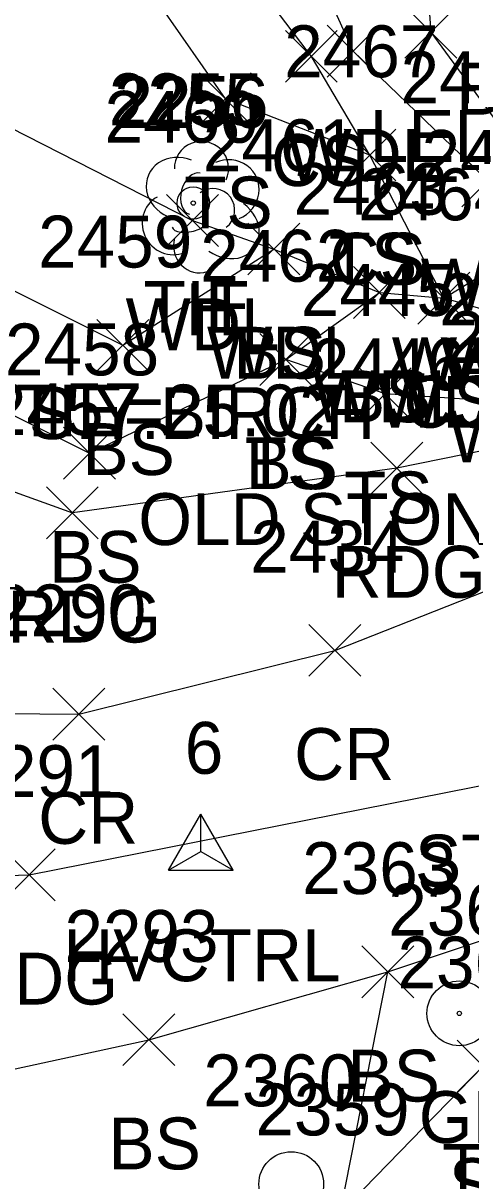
# Model space of a CAD drawing. Extents: x 1512665 to 1513714, y 110636 to 112816.
# Drawn here: x 1513022.1 to 1513039.38, y 110740.23 to 110784.88 of the extents above; entities that cross this region are included whole.
import ezdxf

# ---------------------------------------------------------------- set-up
doc = ezdxf.new("R2010")
doc.units = 0
for name, color, linetype in [('C_A', 7, 'Continuous'), ('C_C', 7, 'Continuous'), ('C_I', 7, 'Continuous'), ('CBP', 7, 'Continuous'), ('CPSM', 7, 'Continuous'), ('L_A', 7, 'Continuous'), ('L_C', 7, 'Continuous'), ('L_I', 7, 'Continuous'), ('L_TIC', 7, 'Continuous'), ('LARO', 7, 'Continuous'), ('LAWA', 7, 'Continuous'), ('LELB', 7, 'Continuous'), ('LTD', 7, 'Continuous'), ('P_A', 7, 'Continuous'), ('P_I', 7, 'Continuous'), ('P_TIC', 7, 'Continuous'), ('PEU', 7, 'Continuous'), ('PRC', 7, 'Continuous'), ('R_A', 7, 'Continuous'), ('R_I', 7, 'Continuous'), ('RGP', 7, 'Continuous')]:
    doc.layers.add(name, color=color, linetype=linetype)

msp = doc.modelspace()

# ---------------------------------------------------------------- linework, layer by layer
at = {"layer": 'CBP'}
for radius in [0.625, 0.0833]:
    msp.add_circle((1513028.667, 110777.939), radius, dxfattribs=at)
at = {"layer": 'CPSM'}
for p, q in [((1513027.711, 110752.208), (1513028.961, 110754.373)), ((1513027.711, 110752.208), (1513028.961, 110754.373)), ((1513027.711, 110752.208), (1513028.961, 110754.373)), ((1513027.711, 110752.208), (1513028.961, 110754.373)), ((1513027.711, 110752.208), (1513028.961, 110754.373)), ((1513027.711, 110752.208), (1513028.961, 110754.373)), ((1513030.211, 110752.208), (1513028.961, 110754.373)), ((1513028.961, 110752.929), (1513028.961, 110754.373)), ((1513030.211, 110752.208), (1513028.961, 110754.373)), ((1513028.961, 110752.929), (1513028.961, 110754.373)), ((1513030.211, 110752.208), (1513028.961, 110754.373)), ((1513028.961, 110752.929), (1513028.961, 110754.373)), ((1513030.211, 110752.208), (1513028.961, 110754.373)), ((1513028.961, 110752.929), (1513028.961, 110754.373)), ((1513030.211, 110752.208), (1513028.961, 110754.373)), ((1513028.961, 110752.929), (1513028.961, 110754.373)), ((1513030.211, 110752.208), (1513028.961, 110754.373)), ((1513028.961, 110752.929), (1513028.961, 110754.373)), ((1513027.711, 110752.208), (1513028.961, 110752.929)), ((1513027.711, 110752.208), (1513028.961, 110752.929)), ((1513027.711, 110752.208), (1513028.961, 110752.929)), ((1513027.711, 110752.208), (1513028.961, 110752.929)), ((1513027.711, 110752.208), (1513028.961, 110752.929)), ((1513027.711, 110752.208), (1513028.961, 110752.929)), ((1513028.961, 110752.929), (1513028.961, 110752.929)), ((1513028.961, 110752.929), (1513030.211, 110752.208)), ((1513028.961, 110752.929), (1513028.961, 110752.929)), ((1513028.961, 110752.929), (1513030.211, 110752.208)), ((1513028.961, 110752.929), (1513028.961, 110752.929)), ((1513028.961, 110752.929), (1513030.211, 110752.208)), ((1513028.961, 110752.929), (1513028.961, 110752.929)), ((1513028.961, 110752.929), (1513030.211, 110752.208)), ((1513028.961, 110752.929), (1513028.961, 110752.929)), ((1513028.961, 110752.929), (1513030.211, 110752.208)), ((1513028.961, 110752.929), (1513028.961, 110752.929)), ((1513028.961, 110752.929), (1513030.211, 110752.208)), ((1513027.711, 110752.208), (1513030.211, 110752.208)), ((1513027.711, 110752.208), (1513030.211, 110752.208)), ((1513027.711, 110752.208), (1513030.211, 110752.208)), ((1513027.711, 110752.208), (1513030.211, 110752.208)), ((1513027.711, 110752.208), (1513030.211, 110752.208)), ((1513027.711, 110752.208), (1513030.211, 110752.208))]:
    msp.add_line(p, q, dxfattribs=at)
at = {"layer": 'L_TIC'}
for points in [[(1513036.836, 110783.528), (1513038.836, 110785.528)], [(1513038.836, 110783.528), (1513036.836, 110785.528)], [(1513032.224, 110782.595), (1513034.224, 110784.595)], [(1513034.224, 110782.595), (1513032.224, 110784.595)], [(1513033.839, 110782.794), (1513035.839, 110784.794)], [(1513035.839, 110782.794), (1513033.839, 110784.794)], [(1513028.907, 110780.961), (1513030.907, 110782.961)], [(1513030.907, 110780.961), (1513028.907, 110782.961)], [(1513034.486, 110778.791), (1513036.486, 110780.791)], [(1513036.486, 110778.791), (1513034.486, 110780.791)], [(1513034.486, 110778.791), (1513036.486, 110780.791)], [(1513036.486, 110778.791), (1513034.486, 110780.791)], [(1513039.029, 110777.791), (1513041.029, 110779.791)], [(1513041.029, 110777.791), (1513039.029, 110779.791)], [(1513027.637, 110776.265), (1513029.637, 110778.265)], [(1513029.637, 110776.265), (1513027.637, 110778.265)], [(1513030.778, 110775.166), (1513032.778, 110777.166)], [(1513032.778, 110775.166), (1513030.778, 110777.166)], [(1513030.778, 110775.166), (1513032.778, 110777.166)], [(1513032.778, 110775.166), (1513030.778, 110777.166)], [(1513034.849, 110773.486), (1513036.849, 110775.486)], [(1513036.849, 110773.486), (1513034.849, 110775.486)], [(1513034.849, 110773.486), (1513036.849, 110775.486)], [(1513036.849, 110773.486), (1513034.849, 110775.486)], [(1513037.334, 110773.274), (1513039.334, 110775.274)], [(1513039.334, 110773.274), (1513037.334, 110775.274)], [(1513037.334, 110773.274), (1513039.334, 110775.274)], [(1513039.334, 110773.274), (1513037.334, 110775.274)], [(1513024.948, 110771.452), (1513026.948, 110773.452)], [(1513026.948, 110771.452), (1513024.948, 110773.452)], [(1513031.242, 110770.906), (1513033.242, 110772.906)], [(1513033.242, 110770.906), (1513031.242, 110772.906)], [(1513031.242, 110770.906), (1513033.242, 110772.906)], [(1513033.242, 110770.906), (1513031.242, 110772.906)], [(1513035.074, 110769.584), (1513037.074, 110771.584)], [(1513037.074, 110769.584), (1513035.074, 110771.584)], [(1513023.663, 110767.294), (1513025.663, 110769.294)], [(1513025.663, 110767.294), (1513023.663, 110769.294)], [(1513035.177, 110747.289), (1513037.177, 110749.289)], [(1513037.177, 110747.289), (1513035.177, 110749.289)], [(1513035.177, 110747.289), (1513037.177, 110749.289)], [(1513037.177, 110747.289), (1513035.177, 110749.289)], [(1513025.953, 110744.673), (1513027.953, 110746.673)], [(1513027.953, 110744.673), (1513025.953, 110746.673)], [(1513038.854, 110743.651), (1513040.854, 110745.651)], [(1513040.854, 110743.651), (1513038.854, 110745.651)]]:
    msp.add_lwpolyline(points, dxfattribs=at)
at = {"layer": 'LARO'}
msp.add_lwpolyline([(1513049.569, 110818.823), (1513041.372, 110818.074), (1513037.384, 110818.461), (1513032.798, 110807.288), (1513035.008, 110805.154), (1513035.695, 110803.452), (1513037.122, 110794.042), (1513037.836, 110784.528), (1513042.755, 110777.819), (1513044.267, 110773.75), (1513049.687, 110768.929), (1513050.18, 110764.057), (1513051.082, 110760.646), (1513051.156, 110759.692)], dxfattribs=at)
at = {"layer": 'LAWA'}
msp.add_lwpolyline([(1512988.199, 110800.659), (1513000.869, 110793.798), (1513013.264, 110785.095), (1513028.637, 110777.265), (1513031.778, 110776.166), (1513035.849, 110774.486), (1513038.334, 110774.274), (1513040.786, 110775.756), (1513040.029, 110778.791), (1513034.839, 110783.794), (1513031.373, 110791.45), (1513032.455, 110794.874), (1513030.687, 110802.22), (1513024.783, 110806.061), (1513019.321, 110811.594), (1513012.859, 110814.122), (1513012.233, 110818.887), (1513011.96, 110820.134), (1513029.824, 110821.619), (1513035.802, 110824.023), (1513038.307, 110832.035), (1513040.001, 110853.344)], dxfattribs=at)
at = {"layer": 'LELB'}
for points in [[(1513042.977, 110772.935), (1513038.334, 110774.274), (1513035.486, 110779.791), (1513033.224, 110783.595), (1513025.018, 110794.357), (1513010.115, 110808.489), (1513000.042, 110802.133), (1512999.104, 110815.556), (1513001.845, 110823.582), (1513003.953, 110835.587)], [(1512965.768, 110809.049), (1512985.021, 110794.556), (1513002.316, 110782.838), (1513012.084, 110779.37), (1513025.948, 110772.452), (1513031.778, 110776.166)], [(1512964.105, 110806.986), (1512983.29, 110791.889), (1512999.323, 110779.951), (1513012.212, 110774.48), (1513024.663, 110768.294), (1513032.242, 110771.906), (1513035.849, 110774.486)], [(1513035.486, 110779.791), (1513029.907, 110781.961), (1513022.152, 110793.076), (1513003.312, 110803.67), (1513000.042, 110802.133)], [(1512958.132, 110793.433), (1512973.652, 110777.453), (1512981.607, 110755.641), (1512996.294, 110746.637), (1513006.992, 110744.376), (1513016.029, 110743.308), (1513026.953, 110745.673), (1513036.177, 110748.289)], [(1513041.72, 110768.766), (1513041.422, 110770.227), (1513036.074, 110770.584), (1513032.242, 110771.906)], [(1513018.15, 110683.845), (1513008.389, 110681.438), (1512992.529, 110692.019), (1513011.814, 110705.262), (1513019.652, 110718.711), (1513025.66, 110731.752), (1513034.332, 110738.983), (1513039.854, 110744.651), (1513044.439, 110751.049), (1513044.971, 110754.973), (1513045.977, 110758.546)], [(1512977.643, 110679.977), (1512992.529, 110692.019), (1512998.215, 110725.784), (1513009, 110733.662), (1513019.12, 110734.326), (1513034.332, 110738.983), (1513036.177, 110748.289), (1513044.439, 110751.049)]]:
    msp.add_lwpolyline(points, dxfattribs=at)
at = {"layer": 'LTD'}
msp.add_line((1513028.938, 110777.838), (1513028.938, 110777.838), dxfattribs=at)
msp.add_line((1513028.938, 110777.838), (1513028.938, 110777.838), dxfattribs=at)
msp.add_arc((1513028.985, 110779.272), 1.047, 335.5272, 180.9563, dxfattribs=at)
for centre, major_axis, ratio, start_param, end_param in [((1513028.146, 110778.504), (1.21, -0.512), 0.895232, 1.570796, 4.712389), ((1513029.98, 110778.421), (-1.141, -0.483), 0.949671, 1.570796, 4.712389), ((1513028.73, 110778.296), (-0.208, -0.792), 0.645439, 3.141593, 6.283185), ((1513029.438, 110777.671), (-0.5, 0.667), 0.989748, 3.141593, 6.283185), ((1513027.855, 110777.129), (0.584, -1.042), 0.959034, 3.141593, 6.283185), ((1513029.938, 110777.005), (-1.09, 0.792), 0.841452, 1.570796, 4.712389), ((1513028.48, 110777.088), (-0.625, -0.083), 0.423636, 0, 3.141593), ((1513028.939, 110776.338), (0.265, 1.061), 0.942809, 1.570796, 4.712389)]:
    msp.add_ellipse(centre, major_axis=major_axis, ratio=ratio, start_param=start_param, end_param=end_param, dxfattribs=at)
at = {"layer": 'P_TIC'}
for points in [[(1513035.521, 110766.718), (1513037.521, 110768.718)], [(1513037.521, 110766.718), (1513035.521, 110768.718)], [(1513023.004, 110764.991), (1513025.004, 110766.991)], [(1513025.004, 110764.991), (1513023.004, 110766.991)], [(1513023.004, 110764.991), (1513025.004, 110766.991)], [(1513025.004, 110764.991), (1513023.004, 110766.991)], [(1513033.128, 110759.688), (1513035.128, 110761.688)], [(1513035.128, 110759.688), (1513033.128, 110761.688)], [(1513023.25, 110757.228), (1513025.25, 110759.228)], [(1513025.25, 110757.228), (1513023.25, 110759.228)], [(1513021.336, 110751.03), (1513023.336, 110753.03)], [(1513023.336, 110751.03), (1513021.336, 110753.03)]]:
    msp.add_lwpolyline(points, dxfattribs=at)
at = {"layer": 'PEU'}
for points in [[(1512701.918, 111049.687), (1512700.272, 111027.695), (1512701.575, 110993.777), (1512707.634, 110973.739), (1512708.973, 110956.468), (1512713.567, 110946.899), (1512719.219, 110936.541), (1512726.895, 110929.376), (1512741.614, 110919.596), (1512758.159, 110912.379), (1512787.354, 110896.005), (1512813.053, 110887.984), (1512838.367, 110874.777), (1512855.917, 110864.835), (1512882.817, 110848.349), (1512898.24, 110841.366), (1512913.486, 110833.402), (1512927.92, 110827.382), (1512944.462, 110817.212), (1512962.879, 110803.833), (1512982.126, 110789.052), (1512997.253, 110777.445), (1513011.324, 110770.561), (1513024.004, 110765.991)], [(1512908.545, 110823.763), (1512922.462, 110816.848), (1512937.29, 110809.107), (1512956.028, 110794.571), (1512958.132, 110793.433), (1512975.798, 110779.469), (1512988.794, 110763.009), (1513002.098, 110756.133), (1513012.974, 110751.731), (1513022.336, 110752.03), (1513042.715, 110756.056), (1513045.977, 110758.546), (1513043.773, 110764.486), (1513041.72, 110768.766), (1513036.521, 110767.718), (1513024.004, 110765.991)]]:
    msp.add_lwpolyline(points, dxfattribs=at)
at = {"layer": 'PRC'}
msp.add_lwpolyline([(1512910.919, 110828.697), (1512924.695, 110822.052), (1512939.408, 110813.161), (1512959.787, 110799.435), (1512979.162, 110782.894), (1512994.968, 110767.907), (1513005.499, 110762.392), (1513013.716, 110758.318), (1513024.25, 110758.228), (1513034.128, 110760.688), (1513043.773, 110764.486)], dxfattribs=at)
at = {"layer": 'RGP'}
msp.add_line((1513038.935, 110746.689), (1513038.935, 110746.689), dxfattribs=at)
for centre, radius in [((1513038.935, 110746.689), 1.25), ((1513038.935, 110746.689), 0.0833), ((1513032.449, 110740.105), 1.25)]:
    msp.add_circle(centre, radius, dxfattribs=at)

# ---------------------------------------------------------------- texts
at = {"layer": 'C_A'}
for s, p in [('TIE', (1513026.746, 110772.939)), ('HVCTRL', (1513023.654, 110747.929)), ('HVCTRL', (1513023.654, 110747.929)), ('HVCTRL', (1513023.654, 110747.929)), ('HVCTRL', (1513023.654, 110747.929)), ('HVCTRL', (1513023.654, 110747.929)), ('HVCTRL', (1513023.654, 110747.929))]:
    msp.add_text(s, height=2, dxfattribs=at).set_placement(p)
at = {"layer": 'C_C'}
msp.add_text('TIE=25.02', height=2, dxfattribs=at).set_placement((1513021.817, 110768.939))
at = {"layer": 'C_I'}
for s, p in [('2255', (1513025.407, 110780.939)), ('6', (1513028.339, 110755.929)), ('6', (1513028.339, 110755.929)), ('6', (1513028.339, 110755.929)), ('6', (1513028.339, 110755.929)), ('6', (1513028.339, 110755.929)), ('6', (1513028.339, 110755.929))]:
    msp.add_text(s, height=2, dxfattribs=at).set_placement(p)
at = {"layer": 'L_A'}
for s, p in [('BS', (1513038.799, 110781.347)), ('LEL', (1513035.474, 110779.528)), ('CS', (1513031.665, 110778.595)), ('WDL', (1513032.256, 110778.794)), ('TS', (1513028.316, 110776.961)), ('TS', (1513033.895, 110774.791)), ('CS', (1513033.926, 110774.791)), ('WDL', (1513037.447, 110773.791)), ('H', (1513028.371, 110772.838)), ('WDL', (1513026.054, 110772.265)), ('WDL', (1513029.195, 110771.166)), ('BS', (1513030.219, 110771.166)), ('WALLS', (1513036.329, 110770.756)), ('WDL', (1513038.203, 110770.756)), ('WDL', (1513033.266, 110769.486)), ('BS', (1513034.29, 110769.486)), ('WDL', (1513035.752, 110769.274)), ('CS', (1513036.775, 110769.274)), ('WALLS', (1513038.52, 110767.935)), ('BS', (1513024.389, 110767.452)), ('TS', (1513030.651, 110766.906)), ('BS', (1513030.683, 110766.906)), ('TS', (1513034.483, 110765.584)), ('BS', (1513023.104, 110763.294)), ('BS', (1513034.618, 110743.289)), ('BS', (1513034.618, 110743.289)), ('BS', (1513025.394, 110740.673)), ('TS', (1513038.264, 110739.651))]:
    msp.add_text(s, height=2, dxfattribs=at).set_placement(p)
at = {"layer": 'L_C'}
for s, p in [('S.Y.BIRCH', (1513022.324, 110768.838)), ('OLD STONE ABUTEMENT', (1513026.543, 110764.75)), ('STONE ABUTMENT', (1513037.222, 110751.578)), ('STONE WING', (1513038.528, 110739.103))]:
    msp.add_text(s, height=2, dxfattribs=at).set_placement(p)
at = {"layer": 'L_I'}
for s, p in [('2467', (1513032.178, 110782.791)), ('2467', (1513032.178, 110782.791)), ('2466', (1513036.667, 110781.791)), ('2256', (1513025.623, 110780.838)), ('2460', (1513025.243, 110780.265)), ('2461', (1513029.038, 110779.166)), ('2461', (1513029.038, 110779.166)), ('2465', (1513037.479, 110778.756)), ('2465', (1513037.479, 110778.756)), ('2463', (1513032.542, 110777.486)), ('2463', (1513032.542, 110777.486)), ('2464', (1513035.027, 110777.274)), ('2464', (1513035.027, 110777.274)), ('2459', (1513022.68, 110775.452)), ('2462', (1513028.935, 110774.906)), ('2462', (1513028.935, 110774.906)), ('2445', (1513032.814, 110773.584)), ('2444', (1513038.162, 110773.227)), ('2443', (1513038.46, 110771.766)), ('2458', (1513021.403, 110771.294)), ('2363', (1513032.87, 110751.289)), ('2363', (1513032.87, 110751.289)), ('2293', (1513023.694, 110748.673)), ('2362', (1513036.547, 110747.651)), ('2359', (1513031.064, 110741.983)), ('2359', (1513031.064, 110741.983))]:
    msp.add_text(s, height=2, dxfattribs=at).set_placement(p)
at = {"layer": 'P_A'}
for s, p in [('RDG', (1513034.009, 110762.718)), ('RDG', (1513021.492, 110760.991)), ('RDG', (1513021.492, 110760.991)), ('CR', (1513032.561, 110755.688)), ('CR', (1513022.684, 110753.228)), ('RDG', (1513019.825, 110747.03))]:
    msp.add_text(s, height=2, dxfattribs=at).set_placement(p)
at = {"layer": 'P_I'}
for s, p in [('2443', (1513038.46, 110771.766)), ('2446', (1513033.206, 110770.718)), ('2457', (1513020.744, 110768.991)), ('2457', (1513020.744, 110768.991)), ('2434', (1513030.868, 110763.688)), ('2290', (1513020.904, 110761.228)), ('2291', (1513019.643, 110755.03))]:
    msp.add_text(s, height=2, dxfattribs=at).set_placement(p)
at = {"layer": 'R_A'}
msp.add_text('GP', height=2, dxfattribs=at).set_placement((1513037.368, 110741.689))
at = {"layer": 'R_I'}
for s, p in [('2361', (1513036.195, 110749.689)), ('2360', (1513029.055, 110743.105))]:
    msp.add_text(s, height=2, dxfattribs=at).set_placement(p)

doc.saveas('drawing.dxf')
